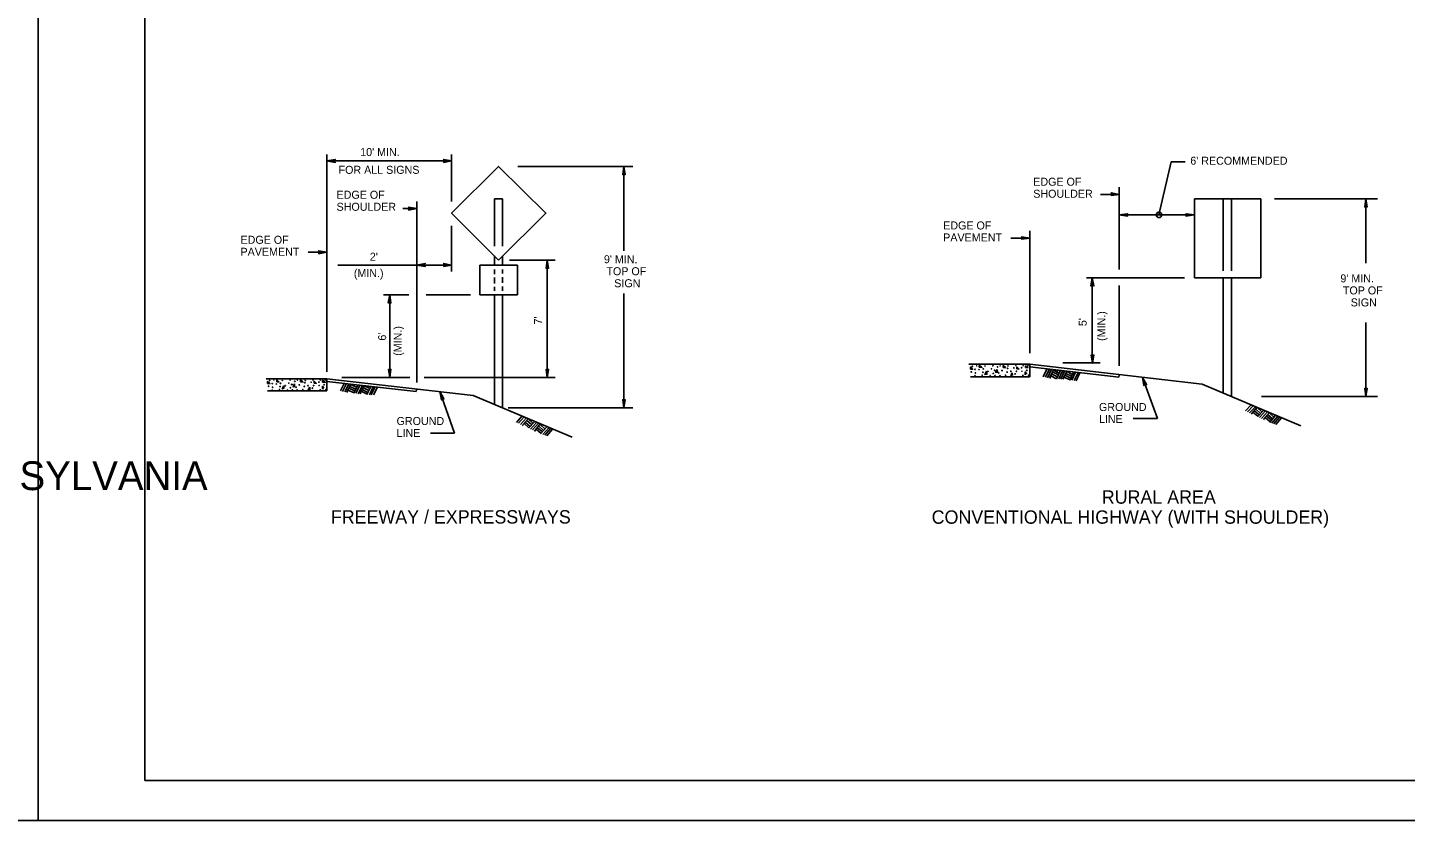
# Model space of a CAD drawing. Extents: x 644358 to 648627, y 294594 to 295782.
# Drawn here: x 646877 to 647394, y 294594 to 294891 of the extents above; entities that cross this region are included whole.
import ezdxf

# ---------------------------------------------------------------- set-up
doc = ezdxf.new("R2010")
doc.units = 0
for name, color, linetype in [('1', 7, 'Continuous'), ('2', 7, 'Continuous'), ('4', 7, 'Continuous'), ('PLT-BNDY', 7, 'Continuous')]:
    doc.layers.add(name, color=color, linetype=linetype)

msp = doc.modelspace()

# ---------------------------------------------------------------- linework, layer by layer
at = {"layer": '1'}
for p, q in [((646921.31, 295172.63), (646921.31, 294608.63)), ((647259.44, 294762.63), (647258.06, 294759.75)), ((647260.31, 294762.5), (647258.94, 294759.63)), ((647261.06, 294762.38), (647259.69, 294759.38)), ((647261.94, 294762.25), (647260.44, 294759.38)), ((647263.06, 294759), (647260.94, 294760.13)), ((647263.44, 294759.75), (647261.19, 294760.88)), ((647263.81, 294760.5), (647261.56, 294761.63)), ((647264.06, 294761.13), (647261.94, 294762.25)), ((647264.44, 294762), (647263.06, 294759)), ((647263.69, 294762), (647263.31, 294762.13)), ((647265.31, 294762), (647263.94, 294759)), ((647266.06, 294761.88), (647264.69, 294758.88)), ((647266.94, 294761.75), (647265.44, 294758.88)), ((647268.44, 294759.25), (647266.19, 294760.38)), ((647268.69, 294760), (647266.56, 294761)), ((647269.06, 294760.63), (647266.94, 294761.75)), ((647267.81, 294761.63), (647267.44, 294761.75)), ((647269.44, 294761.5), (647268.06, 294758.5)), ((647270.19, 294761.5), (647268.81, 294758.5)), ((647271.19, 294761.38), (647269.69, 294758.38)), ((647271.81, 294761.25), (647270.44, 294758.25)), ((646996.06, 294757.25), (646994.69, 294754.5)), ((646996.94, 294757.25), (646995.44, 294754.25)), ((646997.81, 294757), (646996.31, 294754.13)), ((646998.56, 294757), (646997.06, 294754)), ((646999.81, 294753.75), (646997.44, 294754.75)), ((646999.94, 294754.5), (646997.81, 294755.5)), ((647000.31, 294755.13), (646998.19, 294756.13)), ((647000.69, 294755.88), (646998.44, 294756.88)), ((647001.19, 294756.63), (646999.69, 294753.63)), ((647000.19, 294756.63), (646999.94, 294756.75)), ((647001.94, 294756.5), (647000.44, 294753.63)), ((647002.81, 294756.38), (647001.31, 294753.38)), ((647003.44, 294756.38), (647002.06, 294753.38)), ((647004.94, 294753.88), (647002.81, 294755)), ((647005.31, 294754.63), (647003.06, 294755.75)), ((647005.81, 294755.38), (647003.44, 294756.38)), ((647004.44, 294756.13), (647004.06, 294756.38)), ((647006.06, 294756.13), (647004.56, 294753.13)), ((647006.94, 294756), (647005.56, 294753)), ((647007.69, 294756), (647006.19, 294753)), ((647008.56, 294755.88), (647007.06, 294753)), ((647260.94, 294759.25), (647260.56, 294759.5)), ((647268.19, 294758.63), (647265.81, 294759.63)), ((647300.94, 294744.13), (647295.31, 294759.5)), ((646997.44, 294754), (646997.06, 294754.13)), ((647004.69, 294753.25), (647002.44, 294754.38)), ((647037.44, 294738.75), (647031.94, 294754.25)), ((647062.81, 294745.13), (647060.69, 294742.63)), ((647063.56, 294744.75), (647061.44, 294742.38)), ((647335.94, 294749.25), (647333.81, 294747)), ((647336.69, 294748.88), (647334.56, 294746.63)), ((647337.56, 294748.5), (647335.31, 294746.25)), ((647338.19, 294748.38), (647336.06, 294745.88)), ((647336.31, 294745.75), (647336.06, 294746)), ((647338.44, 294745), (647336.56, 294746.5)), ((647338.94, 294745.5), (647337.19, 294747)), ((647339.44, 294746), (647337.56, 294747.75)), ((647339.94, 294746.63), (647338.19, 294748.25)), ((647340.56, 294747.13), (647338.44, 294744.88)), ((647341.31, 294747), (647339.06, 294744.5)), ((647342.06, 294746.63), (647339.81, 294744.13)), ((647342.69, 294746.25), (647340.56, 294743.88)), ((647343.06, 294742.88), (647341.19, 294744.5)), ((647343.56, 294743.5), (647341.69, 294745)), ((647343.94, 294744), (647342.06, 294745.63)), ((647344.56, 294744.5), (647342.69, 294746.25)), ((647345.06, 294745.38), (647342.94, 294742.75)), ((647343.56, 294745.88), (647343.31, 294746)), ((647345.94, 294745), (647343.69, 294742.5)), ((647346.56, 294744.63), (647344.44, 294742.13)), ((647064.44, 294744.38), (647062.19, 294742)), ((647065.06, 294744), (647062.94, 294741.63)), ((647063.19, 294741.5), (647062.94, 294741.75)), ((647065.31, 294740.75), (647063.44, 294742.38)), ((647065.81, 294741.25), (647064.06, 294742.75)), ((647066.31, 294741.88), (647064.44, 294743.5)), ((647066.81, 294742.38), (647065.06, 294744)), ((647067.44, 294743), (647065.31, 294740.63)), ((647068.19, 294742.63), (647065.94, 294740.25)), ((647068.94, 294742.38), (647066.69, 294739.88)), ((647069.56, 294742.13), (647067.44, 294739.5)), ((647067.81, 294739.5), (647067.44, 294739.63)), ((647069.94, 294738.63), (647068.06, 294740.25)), ((647070.44, 294739.25), (647068.56, 294740.75)), ((647070.81, 294739.75), (647068.94, 294741.38)), ((647071.44, 294740.25), (647069.56, 294742)), ((647071.94, 294741), (647069.81, 294738.63)), ((647070.44, 294741.63), (647070.19, 294741.88)), ((647072.81, 294740.75), (647070.56, 294738.25)), ((647073.44, 294740.38), (647071.31, 294738)), ((647074.19, 294740.13), (647072.06, 294737.75)), ((647340.94, 294743.75), (647340.56, 294744)), ((647347.31, 294744.38), (647345.19, 294741.88)), ((647707.31, 294608.63), (646921.31, 294608.63)), ((646921.31, 294608.63), (647507.31, 294608.63))]:
    msp.add_line(p, q, dxfattribs=at)
for points in [[(647276.06, 294794), (647276.31, 294794.13), (647276.44, 294796.88), (647276.06, 294794), (647275.94, 294793.88), (647276.44, 294796.88), (647276.69, 294794.13), (647276.81, 294794), (647276.44, 294796.88), (647277.06, 294793.88), (647276.81, 294794)], [(647012.69, 294787.5), (647012.94, 294787.63), (647013.19, 294790.5), (647012.69, 294787.5), (647012.56, 294787.5), (647013.19, 294790.5), (647013.31, 294787.63), (647013.44, 294787.5), (647013.19, 294790.5), (647013.56, 294787.5), (647013.44, 294787.5)], [(647276.94, 294767.88), (647276.69, 294767.75), (647276.56, 294764.88), (647276.94, 294767.88), (647277.06, 294768), (647276.56, 294764.88), (647276.44, 294767.75), (647276.19, 294767.88), (647276.56, 294764.88), (647276.06, 294768), (647276.19, 294767.88)], [(647013.44, 294762.38), (647013.31, 294762.25), (647013.19, 294759.5), (647013.44, 294762.38), (647013.56, 294762.63), (647013.19, 294759.5), (647013.06, 294762.25), (647012.81, 294762.38), (647013.19, 294759.5), (647012.69, 294762.63), (647012.81, 294762.38)], [(647295.94, 294756.63), (647296.06, 294756.88), (647295.31, 294759.5), (647295.94, 294756.63), (647295.81, 294756.5), (647295.31, 294759.5), (647296.44, 294757), (647296.69, 294757), (647295.31, 294759.5), (647296.81, 294756.88), (647296.69, 294757)], [(647032.56, 294751.38), (647032.81, 294751.5), (647031.94, 294754.25), (647032.56, 294751.38), (647032.56, 294751.13), (647031.94, 294754.25), (647032.94, 294751.5), (647033.19, 294751.5), (647031.94, 294754.25), (647033.44, 294751.5), (647033.19, 294751.5)]]:
    msp.add_lwpolyline(points, dxfattribs=at)
for points in [[(647230.81, 294762.63), (647230.81, 294763.5), (647231.56, 294762.63)], [(647234.06, 294763.38), (647234.06, 294764), (647235.06, 294763.38)], [(647236.81, 294761.88), (647236.94, 294760.75), (647236.19, 294760.63)], [(647240.81, 294762.5), (647240.94, 294761.5), (647240.19, 294761.5)], [(647243.06, 294763.25), (647243.06, 294764), (647243.94, 294763.25)], [(647246.44, 294761.25), (647246.56, 294760.5), (647245.94, 294760.25)], [(647248.19, 294762.75), (647248.19, 294763.5), (647248.94, 294762.75)], [(647251.31, 294760.5), (647251.31, 294761.63), (647251.81, 294761)], [(647251.44, 294763.25), (647251.44, 294763.88), (647252.31, 294763.25)], [(646967.31, 294757.25), (646967.31, 294758), (646968.19, 294757.25)], [(646970.81, 294757.88), (646970.81, 294758.63), (646971.56, 294757.88)], [(646973.44, 294756.38), (646973.44, 294755.5), (646972.81, 294755.25)], [(646977.44, 294757.13), (646977.44, 294756.13), (646976.94, 294756)], [(646979.69, 294757.88), (646979.69, 294758.63), (646980.56, 294757.88)], [(646983.19, 294755.88), (646983.19, 294755), (646982.56, 294754.88)], [(646984.81, 294757.38), (646984.81, 294758.13), (646985.56, 294757.38)], [(646987.94, 294757.75), (646987.94, 294758.5), (646988.94, 294757.75)], [(646987.94, 294755.13), (646987.94, 294756.25), (646988.31, 294755.75)]]:
    msp.add_lwpolyline(points, close=True, dxfattribs=at)
for centre, radius in [((647301.43, 294820.46), 1.04), ((647231.1, 294761.66), 0.0979), ((647231.5, 294763.74), 0.0979), ((647232.51, 294762.61), 0.0979), ((647232.46, 294760.2), 0.056), ((647232.63, 294761.25), 0.0979), ((647233.15, 294763.92), 0.056), ((647233.98, 294762.5), 0.056), ((647235.18, 294760.39), 0.056), ((647235.43, 294761.52), 0.0979), ((647235.57, 294762.78), 0.0979), ((647236.25, 294763.83), 0.056), ((647237.32, 294761.8), 0.0979), ((647238.15, 294760.24), 0.056), ((647238.69, 294762.81), 0.056), ((647239.19, 294763.95), 0.056), ((647239.3, 294761.06), 0.0979), ((647239.83, 294762.28), 0.0979), ((647240.02, 294760.24), 0.0979), ((647240.94, 294763.49), 0.0979), ((647241.4, 294761.25), 0.0979), ((647241.83, 294760.27), 0.056), ((647241.93, 294763.92), 0.056), ((647242.6, 294762.14), 0.0979), ((647243.95, 294760.39), 0.056), ((647244.5, 294761.57), 0.0979), ((647244.69, 294762.93), 0.0979), ((647244.85, 294763.88), 0.056), ((647245.92, 294761.85), 0.0979), ((647247.06, 294763.13), 0.056), ((647247.52, 294760.91), 0.0979), ((647247.79, 294764), 0.056), ((647247.98, 294761.88), 0.0979), ((647249.96, 294763.19), 0.0979), ((647250.08, 294761.91), 0.056), ((647250.43, 294760.32), 0.056), ((647250.52, 294763.97), 0.056), ((647251.9, 294762.21), 0.0979), ((647252.36, 294763.94), 0.056), ((647252.55, 294760.44), 0.056), ((646967.71, 294756.29), 0.0979), ((646968.1, 294758.38), 0.0979), ((646969.11, 294757.25), 0.0979), ((646969.07, 294754.83), 0.056), ((646969.24, 294755.89), 0.0979), ((646969.76, 294758.55), 0.056), ((646970.59, 294757.13), 0.056), ((646971.79, 294755.03), 0.056), ((646972.04, 294756.15), 0.0979), ((646972.18, 294757.41), 0.0979), ((646972.86, 294758.46), 0.056), ((646973.93, 294756.44), 0.0979), ((646974.76, 294754.87), 0.056), ((646975.3, 294757.44), 0.056), ((646975.8, 294758.59), 0.056), ((646975.91, 294755.7), 0.0979), ((646976.43, 294756.92), 0.0979), ((646976.63, 294754.87), 0.0979), ((646977.55, 294758.13), 0.0979), ((646978.01, 294755.89), 0.0979), ((646978.44, 294754.91), 0.056), ((646978.53, 294758.55), 0.056), ((646979.21, 294756.77), 0.0979), ((646980.56, 294755.03), 0.056), ((646981.11, 294756.2), 0.0979), ((646981.3, 294757.56), 0.0979), ((646981.46, 294758.51), 0.056), ((646982.53, 294756.49), 0.0979), ((646983.67, 294757.77), 0.056), ((646984.13, 294755.55), 0.0979), ((646984.4, 294758.63), 0.056), ((646984.58, 294756.52), 0.0979), ((646986.57, 294757.83), 0.0979), ((646986.69, 294756.54), 0.056), ((646987.04, 294754.96), 0.056), ((646987.13, 294758.6), 0.056), ((646988.5, 294756.85), 0.0979), ((646988.97, 294758.57), 0.056), ((646989.16, 294755.08), 0.056)]:
    msp.add_circle(centre, radius, dxfattribs=at)
at = {"layer": '2'}
for p, q in [((647055.44, 294826.5), (647052.44, 294826.5)), ((647052.44, 294826.5), (647052.44, 294808.75)), ((647055.44, 294826.5), (647055.44, 294808.75)), ((647314.69, 294826.5), (647314.69, 294796.88)), ((647339.56, 294826.5), (647314.69, 294826.5)), ((647325.44, 294826.5), (647325.44, 294799.5)), ((647328.56, 294826.5), (647328.56, 294799.5)), ((647339.56, 294796.88), (647339.56, 294826.5)), ((647046.94, 294790.5), (647046.94, 294801.63)), ((647046.94, 294801.63), (647061.06, 294801.63)), ((647052.44, 294805.13), (647052.44, 294801.63)), ((647055.44, 294805), (647055.44, 294801.63)), ((647061.06, 294801.63), (647061.06, 294790.5)), ((647052.44, 294798.25), (647052.44, 294800)), ((647052.44, 294794.75), (647052.44, 294797)), ((647055.44, 294798.5), (647055.44, 294800)), ((647055.44, 294795), (647055.44, 294797.13)), ((647314.69, 294796.88), (647339.56, 294796.88)), ((647325.44, 294796.88), (647325.44, 294753.63)), ((647328.56, 294796.88), (647328.56, 294752.38)), ((647052.44, 294792), (647052.44, 294793.5)), ((647055.44, 294792), (647055.44, 294793.63)), ((647061.06, 294790.5), (647046.94, 294790.5)), ((647052.44, 294790.5), (647052.44, 294749.5)), ((647055.44, 294790.5), (647055.44, 294748.13)), ((647253.06, 294764.5), (647230.19, 294764.5)), ((647253.06, 294764.5), (647253.06, 294759.75)), ((647253.06, 294764.5), (647317.56, 294757)), ((647253.06, 294763.5), (647286.44, 294759.63)), ((647286.56, 294760.5), (647286.44, 294759.63)), ((646989.56, 294759), (646966.81, 294759)), ((646989.56, 294759), (646989.56, 294754.5)), ((646989.56, 294759), (647044.44, 294752.75)), ((646989.56, 294758), (647023.06, 294754.25)), ((647023.31, 294755.25), (647023.06, 294754.25)), ((647253.06, 294759.75), (647230.81, 294759.75)), ((647317.56, 294757), (647354.56, 294741.38)), ((646989.56, 294754.5), (646967.31, 294754.5)), ((647044.44, 294752.75), (647081.44, 294737.25))]:
    msp.add_line(p, q, dxfattribs=at)
msp.add_lwpolyline([(647053.94, 294803.5), (647071.69, 294821.13), (647053.94, 294838.63), (647036.31, 294821.13)], close=True, dxfattribs=at)
at = {"layer": '4'}
for p, q in [((646989.56, 294843.13), (646989.56, 294761.62)), ((647036.31, 294843.13), (647036.31, 294825.5)), ((647036.31, 294840.75), (646989.56, 294840.75)), ((647104.29, 294838.63), (647061.15, 294838.63)), ((647100.84, 294838.63), (647100.84, 294807)), ((647301.44, 294820.5), (647306.06, 294840.38)), ((647306.06, 294840.38), (647311.31, 294840.38)), ((647279.56, 294828.13), (647286.56, 294828.13)), ((647286.56, 294830.88), (647286.56, 294800)), ((647018.06, 294822.88), (647023.31, 294822.88)), ((647023.31, 294825.5), (647023.31, 294757.63)), ((647383.28, 294826.5), (647344.74, 294826.5)), ((647378.94, 294826.5), (647378.94, 294802.43)), ((647314.69, 294820.5), (647286.56, 294820.5)), ((647036.31, 294816.38), (647036.31, 294799.25)), ((647245.94, 294811.75), (647253.06, 294811.75)), ((647253.06, 294814.5), (647253.06, 294768.63)), ((646982.56, 294806.5), (646989.56, 294806.5)), ((647036.31, 294801.63), (646993.65, 294801.63)), ((647075.17, 294803.5), (647058.06, 294803.5)), ((647072.19, 294803.5), (647072.19, 294759.5)), ((647311.06, 294796.88), (647274.31, 294796.88)), ((647276.44, 294796.88), (647276.44, 294765)), ((647100.84, 294748.13), (647100.84, 294791)), ((647286.56, 294794), (647286.56, 294763.88)), ((647020.31, 294790.5), (647010.81, 294790.5)), ((647013.19, 294790.5), (647013.19, 294759.5)), ((647043.44, 294790.5), (647026.81, 294790.5)), ((647378.94, 294752.38), (647378.94, 294780.2)), ((647279.44, 294765), (647265.44, 294765)), ((647020.69, 294759.5), (646995.16, 294759.5)), ((647075.17, 294759.5), (647026.06, 294759.5)), ((647383.28, 294752.38), (647339.87, 294752.38)), ((647104.29, 294748.13), (647057.48, 294748.13)), ((647300.94, 294744.13), (647291.81, 294744.13)), ((647037.44, 294738.75), (647028.44, 294738.75))]:
    msp.add_line(p, q, dxfattribs=at)
for points in [[(646992.56, 294840.25), (646992.44, 294840.5), (646989.56, 294840.75), (646992.56, 294840.25), (646992.69, 294840.13), (646989.56, 294840.75), (646992.44, 294840.88), (646992.56, 294841.13), (646989.56, 294840.75), (646992.69, 294841.25), (646992.56, 294841.13)], [(647033.44, 294841.13), (647033.56, 294840.88), (647036.31, 294840.75), (647033.44, 294841.13), (647033.31, 294841.25), (647036.31, 294840.75), (647033.56, 294840.5), (647033.44, 294840.38), (647036.31, 294840.75), (647033.31, 294840.13), (647033.44, 294840.38)], [(647100.59, 294835.63), (647100.72, 294835.75), (647100.84, 294838.63), (647100.59, 294835.63), (647100.47, 294835.5), (647100.84, 294838.63), (647100.97, 294835.75), (647101.22, 294835.63), (647100.84, 294838.63), (647101.34, 294835.5), (647101.22, 294835.63)], [(647283.69, 294828.5), (647283.81, 294828.38), (647286.56, 294828.13), (647283.69, 294828.5), (647283.56, 294828.75), (647286.56, 294828.13), (647283.81, 294828), (647283.69, 294827.88), (647286.56, 294828.13), (647283.56, 294827.75), (647283.69, 294827.88)], [(647020.31, 294823.25), (647020.44, 294823), (647023.31, 294822.88), (647020.31, 294823.25), (647020.19, 294823.38), (647023.31, 294822.88), (647020.44, 294822.63), (647020.31, 294822.5), (647023.31, 294822.88), (647020.19, 294822.25), (647020.31, 294822.5)], [(647378.69, 294823.5), (647378.81, 294823.63), (647378.94, 294826.5), (647378.69, 294823.5), (647378.56, 294823.38), (647378.94, 294826.5), (647379.06, 294823.63), (647379.31, 294823.5), (647378.94, 294826.5), (647379.44, 294823.38), (647379.31, 294823.5)], [(647289.56, 294820.13), (647289.44, 294820.38), (647286.56, 294820.5), (647289.56, 294820.13), (647289.69, 294820), (647286.56, 294820.5), (647289.44, 294820.5), (647289.56, 294820.75), (647286.56, 294820.5), (647289.69, 294820.88), (647289.56, 294820.75)], [(647311.81, 294820.75), (647311.94, 294820.5), (647314.69, 294820.5), (647311.81, 294820.75), (647311.56, 294820.88), (647314.69, 294820.5), (647311.94, 294820.38), (647311.81, 294820.13), (647314.69, 294820.5), (647311.56, 294820), (647311.81, 294820.13)], [(647250.06, 294812.13), (647250.19, 294811.88), (647253.06, 294811.75), (647250.06, 294812.13), (647249.94, 294812.25), (647253.06, 294811.75), (647250.19, 294811.63), (647250.19, 294811.5), (647253.06, 294811.75), (647249.94, 294811.38), (647250.19, 294811.5)], [(646986.69, 294806.88), (646986.81, 294806.63), (646989.56, 294806.5), (646986.69, 294806.88), (646986.44, 294807), (646989.56, 294806.5), (646986.81, 294806.25), (646986.69, 294806.13), (646989.56, 294806.5), (646986.44, 294805.88), (646986.69, 294806.13)], [(647026.19, 294801.25), (647026.06, 294801.5), (647023.31, 294801.63), (647026.19, 294801.25), (647026.44, 294801.13), (647023.31, 294801.63), (647026.06, 294801.88), (647026.19, 294802), (647023.31, 294801.63), (647026.44, 294802.25), (647026.19, 294802)], [(647033.44, 294802.13), (647033.56, 294801.88), (647036.31, 294801.63), (647033.44, 294802.13), (647033.31, 294802.25), (647036.31, 294801.63), (647033.56, 294801.5), (647033.44, 294801.25), (647036.31, 294801.63), (647033.31, 294801.13), (647033.44, 294801.25)], [(647071.94, 294800.5), (647072.06, 294800.63), (647072.19, 294803.5), (647071.94, 294800.5), (647071.81, 294800.38), (647072.19, 294803.5), (647072.31, 294800.63), (647072.56, 294800.63), (647072.19, 294803.5), (647072.69, 294800.38), (647072.56, 294800.63)], [(647072.56, 294762.5), (647072.31, 294762.38), (647072.19, 294759.5), (647072.56, 294762.5), (647072.69, 294762.63), (647072.19, 294759.5), (647072.06, 294762.38), (647071.94, 294762.5), (647072.19, 294759.5), (647071.81, 294762.63), (647071.94, 294762.5)], [(647378.69, 294755.38), (647378.81, 294755.25), (647378.94, 294752.38), (647378.69, 294755.38), (647378.56, 294755.5), (647378.94, 294752.38), (647379.06, 294755.25), (647379.31, 294755.38), (647378.94, 294752.38), (647379.44, 294755.5), (647379.31, 294755.38)], [(647100.59, 294751.13), (647100.72, 294751), (647100.84, 294748.13), (647100.59, 294751.13), (647100.47, 294751.25), (647100.84, 294748.13), (647100.97, 294751), (647101.22, 294751.13), (647100.84, 294748.13), (647101.34, 294751.25), (647101.22, 294751.13)]]:
    msp.add_lwpolyline(points, dxfattribs=at)
at = {"layer": 'PLT-BNDY'}
for points in [[(646040.31, 295187.63), (646881.31, 295187.63), (646881.31, 294593.63), (646040.31, 294593.63)], [(646881.31, 295187.63), (647722.31, 295187.63), (647722.31, 294593.63), (646881.31, 294593.63)]]:
    msp.add_lwpolyline(points, close=True, dxfattribs=at)

# ---------------------------------------------------------------- texts
at = {"layer": '1'}
for s, height, p in [(" 6' RECOMMENDED", 3, (647312.06, 294839.25)), ('EDGE OF', 3, (647254.31, 294831.38)), ('EDGE OF', 3, (646993.19, 294826.5)), ('SHOULDER', 3, (647254.31, 294826.88)), ('SHOULDER', 3, (646993.19, 294822)), ('EDGE OF', 3, (647220.56, 294815)), ('EDGE OF', 3, (646957.19, 294809.63)), ('PAVEMENT', 3, (647220.56, 294810.5)), ('PAVEMENT', 3, (646957.19, 294805.13)), ('GROUND', 3, (647278.94, 294747)), ('GROUND', 3, (647015.69, 294741.75)), ('LINE', 3, (647278.94, 294742.5)), ('LINE', 3, (647015.69, 294737.25)), ('COMMONWEALTH OF PENNSYLVANIA', 10.7828, (646678.9, 294717.36))]:
    msp.add_text(s, height=height, dxfattribs=at).set_placement(p)
for s, p in [("7'", (647070.25, 294779.39)), ("5'", (647274.32, 294778.78)), ('(MIN.)', (647281.35, 294773.25)), ("6'", (647011.78, 294773.35)), ('(MIN.)', (647017.62, 294767.66))]:
    msp.add_text(s, height=3, rotation=90, dxfattribs=at).set_placement(p)
at = {"layer": '2'}
for s, height, p in [("10' MIN.", 3, (647002.05, 294842.5)), ('FOR ALL SIGNS', 3, (646993.94, 294835.84)), ("2'", 3, (647005.67, 294803.29)), ("9' MIN.", 3, (647093.4, 294802.35)), ('(MIN.)', 3, (646999.67, 294797.13)), ('TOP OF', 3, (647094.34, 294797.85)), ('SIGN', 3, (647097.27, 294793.35)), ("9' MIN.", 3, (647369.42, 294795.17)), ('TOP OF', 3, (647370.36, 294790.67)), ('SIGN', 3, (647373.29, 294786.17)), ('RURAL AREA', 5, (647280, 294712.26)), ('FREEWAY / EXPRESSWAYS', 5, (646991.06, 294704.84)), ('CONVENTIONAL HIGHWAY (WITH SHOULDER)', 5, (647216.24, 294704.76))]:
    msp.add_text(s, height=height, dxfattribs=at).set_placement(p)

doc.saveas('drawing.dxf')
